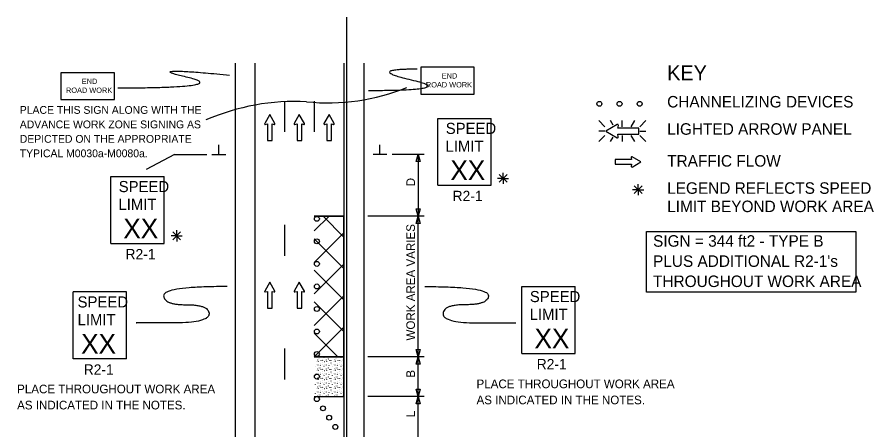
# Model space of a CAD drawing. Extents: x 16247 to 18479, y 5687 to 6964.
# Drawn here: x 16736 to 17429, y 6630 to 6964 of the extents above; entities that cross this region are included whole.
import ezdxf

# ---------------------------------------------------------------- set-up
doc = ezdxf.new("R2010")
doc.units = 0
for name, color, linetype in [('ALI_LEGAL_EX', 7, 'Continuous'), ('MT_SCRATCH_LEVEL_E', 7, 'Continuous'), ('PAVT_EDGE_EX', 7, 'Continuous'), ('TRAFFIC_SIGNS_PR', 7, 'Continuous'), ('TYPICAL_TEXT_DIMEN_EX', 7, 'Continuous'), ('TYPICAL_TEXT_DIMEN_PR', 7, 'Continuous')]:
    doc.layers.add(name, color=color, linetype=linetype)

msp = doc.modelspace()

# ---------------------------------------------------------------- linework, layer by layer
at = {"layer": 'ALI_LEGAL_EX'}
msp.add_line((17002.72, 6964.07), (17002.72, 6147.1), dxfattribs=at)
for points in [[(16952.72, 6896.22), (16952.72, 6871.22)], [(16976.72, 6896.22), (16976.72, 6871.22)], [(16952.72, 6796.22), (16952.72, 6771.22)], [(16952.72, 6696.22), (16952.72, 6671.22)]]:
    msp.add_lwpolyline(points, dxfattribs=at)
at = {"layer": 'MT_SCRATCH_LEVEL_E'}
for p, q in [((16940.72, 6885.31), (16936.61, 6878.07)), ((16944.87, 6878.07), (16940.72, 6885.31)), ((16964.62, 6885.31), (16960.51, 6878.07)), ((16968.77, 6878.07), (16964.62, 6885.31)), ((16988.68, 6885.31), (16984.56, 6878.07)), ((16992.82, 6878.07), (16988.68, 6885.31)), ((16937.09, 6877.38), (16938.87, 6877.7)), ((16938.87, 6877.7), (16938.87, 6864.44)), ((16942.61, 6864.44), (16942.61, 6877.7)), ((16942.61, 6877.7), (16944.39, 6877.38)), ((16960.99, 6877.38), (16962.77, 6877.7)), ((16962.77, 6877.7), (16962.77, 6864.44)), ((16966.51, 6864.44), (16966.51, 6877.7)), ((16966.51, 6877.7), (16968.29, 6877.38)), ((16985.05, 6877.38), (16986.82, 6877.7)), ((16986.82, 6877.7), (16986.82, 6864.44)), ((16990.57, 6864.44), (16990.57, 6877.7)), ((16990.57, 6877.7), (16992.34, 6877.38)), ((16938.87, 6864.44), (16942.61, 6864.44)), ((16962.77, 6864.44), (16966.51, 6864.44)), ((16986.82, 6864.44), (16990.57, 6864.44)), ((17233.37, 6848.9), (17220.11, 6848.9)), ((17220.11, 6848.9), (17220.11, 6845.16)), ((17233.05, 6850.68), (17233.37, 6848.9)), ((17240.98, 6847.05), (17233.74, 6851.16)), ((17220.11, 6845.16), (17233.37, 6845.16)), ((17233.37, 6845.16), (17233.05, 6843.39)), ((17233.74, 6842.91), (17240.98, 6847.05)), ((16940.72, 6749.79), (16936.61, 6742.55)), ((16944.87, 6742.55), (16940.72, 6749.79)), ((16964.62, 6749.79), (16960.51, 6742.55)), ((16968.77, 6742.55), (16964.62, 6749.79)), ((16937.09, 6741.86), (16938.87, 6742.18)), ((16938.87, 6742.18), (16938.87, 6728.92)), ((16942.61, 6728.92), (16942.61, 6742.18)), ((16942.61, 6742.18), (16944.39, 6741.86)), ((16960.99, 6741.86), (16962.77, 6742.18)), ((16962.77, 6742.18), (16962.77, 6728.92)), ((16966.51, 6728.92), (16966.51, 6742.18)), ((16966.51, 6742.18), (16968.29, 6741.86)), ((16938.87, 6728.92), (16942.61, 6728.92)), ((16962.77, 6728.92), (16966.51, 6728.92))]:
    msp.add_line(p, q, dxfattribs=at)
for centre, start, end in [((16937.02, 6877.84), 150.42484, 279.96381), ((16944.46, 6877.84), 260.03619, 29.77312), ((16960.92, 6877.84), 150.42484, 279.96381), ((16968.36, 6877.84), 260.03619, 29.77312), ((16984.97, 6877.84), 150.42484, 279.96381), ((16992.41, 6877.84), 260.03619, 29.77312), ((17233.51, 6850.76), 60.42484, 189.96381), ((17233.51, 6843.32), 170.03619, 299.77312), ((16937.02, 6742.32), 150.42484, 279.96381), ((16944.46, 6742.32), 260.03619, 29.77312), ((16960.92, 6742.32), 150.42484, 279.96381), ((16968.36, 6742.32), 260.03619, 29.77312)]:
    msp.add_arc(centre, 0.463, start, end, dxfattribs=at)
at = {"layer": 'PAVT_EDGE_EX'}
for p, q in [((16912.72, 6926.76), (16912.72, 6233.21)), ((16928.72, 6926.76), (16928.72, 6233.21)), ((17000.72, 6926.76), (17000.72, 6233.21)), ((17016.72, 6926.76), (17016.72, 6233.21)), ((17000.72, 6803.12), (16976.72, 6803.12)), ((16976.72, 6803.12), (17000.72, 6803.12)), ((16976.72, 6791.22), (16988.62, 6803.12)), ((17000.72, 6786.31), (16983.91, 6803.12)), ((17000.72, 6689.4), (17000.72, 6803.12)), ((16976.72, 6765.77), (17000.72, 6789.77)), ((17000.72, 6760.86), (16976.72, 6784.86)), ((16976.72, 6740.31), (17000.72, 6764.31)), ((17000.72, 6735.4), (16976.72, 6759.4)), ((16976.72, 6714.86), (17000.72, 6738.86)), ((17000.72, 6709.95), (16976.72, 6733.95)), ((16976.72, 6689.4), (17000.72, 6713.4)), ((16995.81, 6689.4), (16976.72, 6708.49)), ((16976.72, 6689.4), (17000.72, 6689.4)), ((16976.72, 6689.4), (17000.72, 6689.4)), ((17000.72, 6689.4), (16976.72, 6689.4)), ((16976.72, 6689.4), (16976.72, 6689.4)), ((16977.65, 6689.04), (16977.7, 6689.16)), ((16984.53, 6689.04), (16984.59, 6689.16)), ((16991.42, 6689.04), (16991.47, 6689.16)), ((16998.31, 6689.04), (16998.36, 6689.16)), ((17000.72, 6657.34), (17000.72, 6689.4)), ((16977.65, 6681.76), (16977.7, 6681.87)), ((16978.22, 6685.72), (16978.27, 6685.64)), ((16978.27, 6683.51), (16978.32, 6683.43)), ((16979.55, 6682.93), (16979.56, 6682.82)), ((16979.67, 6686.84), (16979.72, 6686.96)), ((16979.75, 6685.58), (16979.8, 6685.5)), ((16980.43, 6687.8), (16980.48, 6687.73)), ((16981.17, 6687.78), (16981.22, 6687.7)), ((16981.39, 6683.79), (16981.44, 6683.9)), ((16981.58, 6682.59), (16981.63, 6682.51)), ((16982.04, 6686.4), (16982.09, 6686.32)), ((16983.31, 6684.66), (16983.37, 6684.58)), ((16983.36, 6683.26), (16983.41, 6683.37)), ((16983.49, 6686.55), (16983.54, 6686.66)), ((16984.53, 6681.76), (16984.59, 6681.87)), ((16985.1, 6685.72), (16985.16, 6685.64)), ((16985.15, 6683.51), (16985.21, 6683.43)), ((16986.44, 6682.93), (16986.45, 6682.82)), ((16986.56, 6686.84), (16986.61, 6686.96)), ((16986.64, 6685.58), (16986.69, 6685.5)), ((16987.32, 6687.8), (16987.37, 6687.73)), ((16988.06, 6687.78), (16988.11, 6687.7)), ((16988.28, 6683.79), (16988.33, 6683.9)), ((16988.47, 6682.59), (16988.52, 6682.51)), ((16988.92, 6686.4), (16988.98, 6686.32)), ((16990.2, 6684.66), (16990.25, 6684.58)), ((16990.24, 6683.26), (16990.3, 6683.37)), ((16990.37, 6686.55), (16990.42, 6686.66)), ((16991.42, 6681.76), (16991.47, 6681.87)), ((16991.99, 6685.72), (16992.04, 6685.64)), ((16992.04, 6683.51), (16992.09, 6683.43)), ((16993.32, 6682.93), (16993.33, 6682.82)), ((16993.44, 6686.84), (16993.49, 6686.96)), ((16993.52, 6685.58), (16993.57, 6685.5)), ((16994.21, 6687.8), (16994.26, 6687.73)), ((16994.94, 6687.78), (16994.99, 6687.7)), ((16995.16, 6683.79), (16995.22, 6683.9)), ((16995.35, 6682.59), (16995.4, 6682.51)), ((16995.81, 6686.4), (16995.86, 6686.32)), ((16997.09, 6684.66), (16997.14, 6684.58)), ((16997.13, 6683.26), (16997.18, 6683.37)), ((16997.26, 6686.55), (16997.31, 6686.66)), ((16998.31, 6681.76), (16998.36, 6681.87)), ((16998.88, 6685.72), (16998.93, 6685.64)), ((16998.93, 6683.51), (16998.98, 6683.43)), ((17000.21, 6682.93), (17000.22, 6682.82)), ((17000.33, 6686.84), (17000.38, 6686.96)), ((17000.41, 6685.58), (17000.46, 6685.5)), ((16977.65, 6674.47), (16977.7, 6674.59)), ((16978.22, 6678.43), (16978.27, 6678.36)), ((16978.27, 6676.22), (16978.32, 6676.15)), ((16979.55, 6675.65), (16979.56, 6675.53)), ((16979.67, 6679.56), (16979.72, 6679.68)), ((16979.75, 6678.29), (16979.8, 6678.22)), ((16980.43, 6680.52), (16980.48, 6680.44)), ((16981.17, 6680.49), (16981.22, 6680.41)), ((16981.39, 6676.5), (16981.44, 6676.62)), ((16981.58, 6675.31), (16981.63, 6675.23)), ((16982.04, 6679.11), (16982.09, 6679.03)), ((16983.31, 6677.37), (16983.37, 6677.3)), ((16983.36, 6675.97), (16983.41, 6676.09)), ((16983.49, 6679.26), (16983.54, 6679.38)), ((16984.53, 6674.47), (16984.59, 6674.59)), ((16985.1, 6678.43), (16985.16, 6678.36)), ((16985.15, 6676.22), (16985.21, 6676.15)), ((16986.44, 6675.65), (16986.45, 6675.53)), ((16986.56, 6679.56), (16986.61, 6679.68)), ((16986.64, 6678.29), (16986.69, 6678.22)), ((16987.32, 6680.52), (16987.37, 6680.44)), ((16988.06, 6680.49), (16988.11, 6680.41)), ((16988.28, 6676.5), (16988.33, 6676.62)), ((16988.47, 6675.31), (16988.52, 6675.23)), ((16988.92, 6679.11), (16988.98, 6679.03)), ((16990.2, 6677.37), (16990.25, 6677.3)), ((16990.24, 6675.97), (16990.3, 6676.09)), ((16990.37, 6679.26), (16990.42, 6679.38)), ((16991.42, 6674.47), (16991.47, 6674.59)), ((16991.99, 6678.43), (16992.04, 6678.36)), ((16992.04, 6676.22), (16992.09, 6676.15)), ((16993.32, 6675.65), (16993.33, 6675.53)), ((16993.44, 6679.56), (16993.49, 6679.68)), ((16993.52, 6678.29), (16993.57, 6678.22)), ((16994.21, 6680.52), (16994.26, 6680.44)), ((16994.94, 6680.49), (16994.99, 6680.41)), ((16995.16, 6676.5), (16995.22, 6676.62)), ((16995.35, 6675.31), (16995.4, 6675.23)), ((16995.81, 6679.11), (16995.86, 6679.03)), ((16997.09, 6677.37), (16997.14, 6677.3)), ((16997.13, 6675.97), (16997.18, 6676.09)), ((16997.26, 6679.26), (16997.31, 6679.38)), ((16998.31, 6674.47), (16998.36, 6674.59)), ((16998.88, 6678.43), (16998.93, 6678.36)), ((16998.93, 6676.22), (16998.98, 6676.15)), ((17000.21, 6675.65), (17000.22, 6675.53)), ((17000.33, 6679.56), (17000.38, 6679.68)), ((17000.41, 6678.29), (17000.46, 6678.22)), ((16977.65, 6667.19), (16977.7, 6667.3)), ((16978.22, 6671.15), (16978.27, 6671.07)), ((16978.27, 6668.94), (16978.32, 6668.86)), ((16979.55, 6668.36), (16979.56, 6668.25)), ((16979.67, 6672.28), (16979.72, 6672.39)), ((16979.75, 6671.01), (16979.8, 6670.93)), ((16980.43, 6673.23), (16980.48, 6673.16)), ((16981.17, 6673.2), (16981.22, 6673.13)), ((16981.39, 6669.22), (16981.44, 6669.34)), ((16981.58, 6668.02), (16981.63, 6667.94)), ((16982.04, 6671.83), (16982.09, 6671.75)), ((16983.31, 6670.09), (16983.37, 6670.01)), ((16983.36, 6668.69), (16983.41, 6668.81)), ((16983.49, 6671.98), (16983.54, 6672.09)), ((16984.53, 6667.19), (16984.59, 6667.3)), ((16985.1, 6671.15), (16985.16, 6671.07)), ((16985.15, 6668.94), (16985.21, 6668.86)), ((16986.44, 6668.36), (16986.45, 6668.25)), ((16986.56, 6672.28), (16986.61, 6672.39)), ((16986.64, 6671.01), (16986.69, 6670.93)), ((16987.32, 6673.23), (16987.37, 6673.16)), ((16988.06, 6673.2), (16988.11, 6673.13)), ((16988.28, 6669.22), (16988.33, 6669.34)), ((16988.47, 6668.02), (16988.52, 6667.94)), ((16988.92, 6671.83), (16988.98, 6671.75)), ((16990.2, 6670.09), (16990.25, 6670.01)), ((16990.24, 6668.69), (16990.3, 6668.81)), ((16990.37, 6671.98), (16990.42, 6672.09)), ((16991.42, 6667.19), (16991.47, 6667.3)), ((16991.99, 6671.15), (16992.04, 6671.07)), ((16992.04, 6668.94), (16992.09, 6668.86)), ((16993.32, 6668.36), (16993.33, 6668.25)), ((16993.44, 6672.28), (16993.49, 6672.39)), ((16993.52, 6671.01), (16993.57, 6670.93)), ((16994.21, 6673.23), (16994.26, 6673.16)), ((16994.94, 6673.2), (16994.99, 6673.13)), ((16995.16, 6669.22), (16995.22, 6669.34)), ((16995.35, 6668.02), (16995.4, 6667.94)), ((16995.81, 6671.83), (16995.86, 6671.75)), ((16997.09, 6670.09), (16997.14, 6670.01)), ((16997.13, 6668.69), (16997.18, 6668.81)), ((16997.26, 6671.98), (16997.31, 6672.09)), ((16998.31, 6667.19), (16998.36, 6667.3)), ((16998.88, 6671.15), (16998.93, 6671.07)), ((16998.93, 6668.94), (16998.98, 6668.86)), ((17000.21, 6668.36), (17000.22, 6668.25)), ((17000.33, 6672.28), (17000.38, 6672.39)), ((17000.41, 6671.01), (17000.46, 6670.93)), ((16978.22, 6663.86), (16978.27, 6663.79)), ((16978.27, 6661.65), (16978.32, 6661.58)), ((16979.55, 6661.08), (16979.56, 6660.96)), ((16979.67, 6664.99), (16979.72, 6665.11)), ((16979.75, 6663.72), (16979.8, 6663.65)), ((16980.43, 6665.95), (16980.48, 6665.87)), ((16981.17, 6665.92), (16981.22, 6665.84)), ((16981.39, 6661.93), (16981.44, 6662.05)), ((16981.58, 6660.74), (16981.63, 6660.66)), ((16982.04, 6664.54), (16982.09, 6664.46)), ((16983.31, 6662.8), (16983.37, 6662.73)), ((16983.36, 6661.4), (16983.41, 6661.52)), ((16983.49, 6664.69), (16983.54, 6664.81)), ((16985.1, 6663.86), (16985.16, 6663.79)), ((16985.15, 6661.65), (16985.21, 6661.58)), ((16986.44, 6661.08), (16986.45, 6660.96)), ((16986.56, 6664.99), (16986.61, 6665.11)), ((16986.64, 6663.72), (16986.69, 6663.65)), ((16987.32, 6665.95), (16987.37, 6665.87)), ((16988.06, 6665.92), (16988.11, 6665.84)), ((16988.28, 6661.93), (16988.33, 6662.05)), ((16988.47, 6660.74), (16988.52, 6660.66)), ((16988.92, 6664.54), (16988.98, 6664.46)), ((16990.2, 6662.8), (16990.25, 6662.73)), ((16990.24, 6661.4), (16990.3, 6661.52)), ((16990.37, 6664.69), (16990.42, 6664.81)), ((16991.99, 6663.86), (16992.04, 6663.79)), ((16992.04, 6661.65), (16992.09, 6661.58)), ((16993.32, 6661.08), (16993.33, 6660.96)), ((16993.44, 6664.99), (16993.49, 6665.11)), ((16993.52, 6663.72), (16993.57, 6663.65)), ((16994.21, 6665.95), (16994.26, 6665.87)), ((16994.94, 6665.92), (16994.99, 6665.84)), ((16995.16, 6661.93), (16995.22, 6662.05)), ((16995.35, 6660.74), (16995.4, 6660.66)), ((16995.81, 6664.54), (16995.86, 6664.46)), ((16997.09, 6662.8), (16997.14, 6662.73)), ((16997.13, 6661.4), (16997.18, 6661.52)), ((16997.26, 6664.69), (16997.31, 6664.81)), ((16998.88, 6663.86), (16998.93, 6663.79)), ((16998.93, 6661.65), (16998.98, 6661.58)), ((17000.21, 6661.08), (17000.22, 6660.96)), ((17000.33, 6664.99), (17000.38, 6665.11)), ((17000.41, 6663.72), (17000.46, 6663.65)), ((16976.72, 6657.34), (17000.72, 6657.34)), ((16976.72, 6657.34), (17000.72, 6657.34)), ((16977.65, 6659.9), (16977.7, 6660.02)), ((16979.67, 6657.7), (16979.72, 6657.82)), ((16980.43, 6658.66), (16980.48, 6658.59)), ((16981.17, 6658.64), (16981.22, 6658.56)), ((16983.49, 6657.41), (16983.54, 6657.52)), ((16984.53, 6659.9), (16984.59, 6660.02)), ((16986.56, 6657.7), (16986.61, 6657.82)), ((16987.32, 6658.66), (16987.37, 6658.59)), ((16988.06, 6658.64), (16988.11, 6658.56)), ((16990.37, 6657.41), (16990.42, 6657.52)), ((16991.42, 6659.9), (16991.47, 6660.02)), ((16993.44, 6657.7), (16993.49, 6657.82)), ((16994.21, 6658.66), (16994.26, 6658.59)), ((16994.94, 6658.64), (16994.99, 6658.56)), ((16997.26, 6657.41), (16997.31, 6657.52)), ((16998.31, 6659.9), (16998.36, 6660.02)), ((17000.33, 6657.7), (17000.38, 6657.82))]:
    msp.add_line(p, q, dxfattribs=at)
at = {"layer": 'TRAFFIC_SIGNS_PR'}
for p, q in [((17076.58, 6882.17), (17119.78, 6882.17)), ((17076.58, 6828.17), (17076.58, 6882.17)), ((17119.78, 6828.17), (17119.78, 6882.17)), ((17206.79, 6880.44), (17211.72, 6875.5)), ((17218.55, 6876.61), (17216.34, 6880.44)), ((17225.87, 6875.5), (17225.87, 6880.44)), ((17233.11, 6875.5), (17235.96, 6880.44)), ((17240.02, 6875.5), (17244.96, 6880.44)), ((17211.72, 6871.95), (17206.79, 6871.95)), ((17206.79, 6863.46), (17211.72, 6868.39)), ((17225.87, 6868.39), (17225.87, 6863.46)), ((17236, 6863.46), (17233.15, 6868.39)), ((17240.02, 6871.95), (17244.96, 6871.95)), ((17240.02, 6868.39), (17244.96, 6863.45)), ((17216.3, 6863.46), (17218.41, 6867.12)), ((16812.01, 6835.14), (16855.21, 6835.14)), ((16812.01, 6781.14), (16812.01, 6835.14)), ((16855.21, 6781.14), (16855.21, 6835.14)), ((17076.58, 6828.17), (17119.78, 6828.17)), ((16812.01, 6781.14), (16855.21, 6781.14)), ((17144.63, 6746.22), (17187.83, 6746.22)), ((17144.63, 6692.22), (17144.63, 6746.22)), ((17187.83, 6692.22), (17187.83, 6746.22)), ((16824.83, 6741.87), (16781.63, 6741.87)), ((16781.63, 6687.87), (16781.63, 6741.87)), ((16824.83, 6687.87), (16824.83, 6741.87)), ((17144.63, 6692.22), (17187.83, 6692.22)), ((16824.83, 6687.87), (16781.63, 6687.87))]:
    msp.add_line(p, q, dxfattribs=at)
for points in [[(16771.8, 6897.5), (16815, 6897.5), (16815, 6919.1), (16771.8, 6919.1)], [(17062.94, 6901.91), (17106.14, 6901.91), (17106.14, 6923.51), (17062.94, 6923.51)], [(17062.94, 6901.91), (17106.14, 6901.91), (17106.14, 6923.51), (17062.94, 6923.51)]]:
    msp.add_lwpolyline(points, close=True, dxfattribs=at)
for points in [[(17221.8, 6877.22), (17212.51, 6871.95), (17221.8, 6866.63)], [(17222.67, 6867.25), (17222.27, 6869.52), (17239.29, 6869.52), (17239.29, 6874.32), (17222.27, 6874.32), (17222.68, 6876.6)]]:
    msp.add_lwpolyline(points, dxfattribs=at)
for centre in [(17207.35, 6893.98), (17223.65, 6893.98), (17239.95, 6893.98), (16978.82, 6801), (16978.82, 6782.79), (16978.82, 6764.57), (16978.82, 6746.36), (16978.82, 6728.15), (16978.82, 6709.93), (16978.82, 6691.72), (16978.82, 6673.5), (16978.82, 6655.29), (16983.79, 6647.78), (16988.76, 6640.27), (16993.73, 6632.77)]:
    msp.add_circle(centre, 2, dxfattribs=at)
for centre, radius, start, end in [((16988.38, 7060.49), 165.74, 263.81853, 292.44581), ((16961.52, 6713.48), 182.45, 87.16713, 113.38058), ((17222.09, 6876.7), 0.598, 350.73078, 118.89165), ((17222.09, 6867.15), 0.597, 241.48329, 9.95933)]:
    msp.add_arc(centre, radius, start, end, dxfattribs=at)
for points in [[(16817.69, 6906.91), (16911.43, 6906.91), (16834.91, 6924.32), (16908.24, 6917.25)], [(17059.88, 6921.99), (17017.37, 6921.99), (17093.89, 6904.57), (17020.55, 6904.57)]]:
    msp.add_open_spline(points, degree=2, dxfattribs=at)
at = {"layer": 'TYPICAL_TEXT_DIMEN_EX'}
msp.add_lwpolyline([(17245.38, 6790.88), (17414.83, 6790.88), (17414.83, 6741.68), (17245.38, 6741.68)], close=True, dxfattribs=at)
at = {"layer": 'TYPICAL_TEXT_DIMEN_PR'}
for p, q in [((16899.6, 6853.12), (16899.6, 6860.91)), ((17029.85, 6853.12), (17029.85, 6860.91)), ((16863.72, 6853.12), (16840.61, 6840.94)), ((16863.72, 6853.12), (16889.72, 6853.12)), ((16893.97, 6853.12), (16905.22, 6853.12)), ((17035.47, 6853.12), (17024.22, 6853.12)), ((17065.72, 6853.12), (17039.72, 6853.12)), ((17059.15, 6847.26), (17060.72, 6853.12)), ((17060.72, 6853.12), (17062.29, 6847.26)), ((17060.72, 6853.12), (17060.72, 6803.12)), ((17060.72, 6847.26), (17059.15, 6847.26)), ((17062.29, 6847.26), (17060.72, 6847.26)), ((17129.48, 6833.74), (17124.95, 6833.74)), ((17126.3, 6836.93), (17132.67, 6830.55)), ((17132.67, 6836.93), (17126.3, 6830.55)), ((17129.48, 6833.74), (17129.48, 6838.2)), ((17129.48, 6833.74), (17132.67, 6833.74)), ((17129.48, 6833.74), (17133.96, 6833.74)), ((17129.48, 6833.74), (17129.48, 6829.24)), ((17235.58, 6827.78), (17241.95, 6821.4)), ((17241.95, 6827.78), (17235.58, 6821.4)), ((17238.76, 6824.59), (17238.76, 6829.05)), ((17238.76, 6824.59), (17234.23, 6824.59)), ((17238.76, 6824.59), (17241.95, 6824.59)), ((17238.76, 6824.59), (17243.24, 6824.59)), ((17238.76, 6824.59), (17238.76, 6820.09)), ((17060.72, 6803.12), (17059.15, 6808.99)), ((17059.15, 6808.99), (17060.72, 6808.99)), ((17060.72, 6808.99), (17062.29, 6808.99)), ((17062.29, 6808.99), (17060.72, 6803.12)), ((17065.72, 6803.12), (17020.02, 6803.12)), ((17059.15, 6797.26), (17060.72, 6803.12)), ((17060.72, 6689.4), (17060.72, 6803.12)), ((17060.72, 6803.12), (17062.29, 6797.26)), ((17060.72, 6797.26), (17059.15, 6797.26)), ((17062.29, 6797.26), (17060.72, 6797.26)), ((16865.4, 6787.3), (16860.87, 6787.3)), ((16862.22, 6790.49), (16868.59, 6784.11)), ((16868.59, 6790.49), (16862.22, 6784.11)), ((16865.4, 6787.3), (16865.4, 6791.76)), ((16865.4, 6787.3), (16868.59, 6787.3)), ((16865.4, 6787.3), (16869.88, 6787.3)), ((16865.4, 6787.3), (16865.4, 6782.8)), ((17060.72, 6689.4), (17059.15, 6695.26)), ((17059.15, 6695.26), (17060.72, 6695.26)), ((17060.72, 6695.26), (17062.29, 6695.26)), ((17062.29, 6695.26), (17060.72, 6689.4)), ((17065.72, 6689.4), (17020.02, 6689.4)), ((17059.15, 6683.54), (17060.72, 6689.4)), ((17060.72, 6657.34), (17060.72, 6689.4)), ((17060.72, 6689.4), (17062.29, 6683.54)), ((17060.72, 6683.54), (17059.15, 6683.54)), ((17062.29, 6683.54), (17060.72, 6683.54)), ((17060.72, 6657.34), (17059.15, 6663.2)), ((17059.15, 6663.2), (17060.72, 6663.2)), ((17060.72, 6663.2), (17062.29, 6663.2)), ((17062.29, 6663.2), (17060.72, 6657.34)), ((17065.72, 6657.34), (17020.02, 6657.34)), ((17059.15, 6651.48), (17060.72, 6657.34)), ((17060.72, 6623.15), (17060.72, 6657.34)), ((17060.72, 6657.34), (17062.29, 6651.48)), ((17060.72, 6651.48), (17059.15, 6651.48)), ((17062.29, 6651.48), (17060.72, 6651.48))]:
    msp.add_line(p, q, dxfattribs=at)
for points in [[(16906.3, 6746.26), (16854.85, 6746.26), (16854.85, 6731.56), (16891.6, 6731.56), (16891.6, 6716.86), (16832.8, 6716.86), (16832.8, 6716.86)], [(17066.17, 6746.26), (17117.62, 6746.26), (17117.62, 6731.56), (17080.87, 6731.56), (17080.87, 6716.86), (17139.67, 6716.86), (17139.67, 6716.86)]]:
    msp.add_open_spline(points, degree=2, dxfattribs=at)

# ---------------------------------------------------------------- texts
at = {"layer": 'TRAFFIC_SIGNS_PR'}
for s, height, p in [('END', 4.31, (17079.82, 6914.43)), ('END', 4.31, (17079.82, 6914.43)), ('END', 4.31, (16788.67, 6910.02)), ('ROAD WORK', 4.31, (17067, 6907.24)), ('ROAD WORK', 4.31, (17067, 6907.24)), ('ROAD WORK', 4.31, (16775.86, 6902.83)), ('PLACE THIS SIGN ALONG WITH THE', 6.3, (16738.49, 6885.91)), ('ADVANCE WORK ZONE SIGNING AS', 6.3, (16738.49, 6874.21)), ('SPEED', 9, (17083.07, 6869.64)), ('DEPICTED ON THE APPROPRIATE', 6.3, (16738.49, 6862.51)), ('LIMIT', 9, (17082.89, 6855.24)), ('TYPICAL M0030a-M0080a.', 6.3, (16738.49, 6850.81)), ('XX', 15.785, (17086.83, 6832.4)), ('SPEED', 9, (16818.5, 6822.61)), ('R2-1', 8.37, (17088.59, 6815.3)), ('LIMIT', 9, (16818.31, 6808.21)), ('XX', 15.785, (16822.26, 6785.37)), ('R2-1', 8.37, (16824.02, 6768.27)), ('SPEED', 9, (16785.25, 6729.34)), ('SPEED', 9, (17151.11, 6733.68)), ('LIMIT', 9, (16785.22, 6714.94)), ('LIMIT', 9, (17150.93, 6719.28)), ('XX', 15.785, (17154.88, 6696.44)), ('XX', 15.785, (16788.14, 6692.1)), ('R2-1', 8.37, (16790.22, 6675)), ('R2-1', 8.37, (17156.64, 6679.35)), ('PLACE THROUGHOUT WORK AREA', 7, (17107.98, 6664.09)), ('PLACE THROUGHOUT WORK AREA', 7, (16736.32, 6659.93)), ('AS INDICATED IN THE NOTES.', 7, (16736.32, 6646.93)), ('AS INDICATED IN THE NOTES.', 7, (17107.98, 6651.09))]:
    msp.add_text(s, height=height, dxfattribs=at).set_placement(p)
at = {"layer": 'TYPICAL_TEXT_DIMEN_EX'}
for s, height, p in [('KEY', 12, (17262.19, 6913.09)), ('CHANNELIZING DEVICES', 9.3, (17262.19, 6891.04)), ('LIGHTED ARROW PANEL', 9.3, (17262.19, 6868.99)), ('TRAFFIC FLOW', 9.3, (17262.19, 6843.19)), ('LEGEND REFLECTS SPEED', 9.3, (17262.19, 6821.24)), ('LIMIT BEYOND WORK AREA', 9.3, (17262.19, 6806.44)), ('SIGN = 344 ft2 - TYPE B', 9.3, (17250.77, 6778.47)), ("PLUS ADDITIONAL R2-1's", 9.3, (17250.77, 6762.17)), ('THROUGHOUT WORK AREA', 9.3, (17250.77, 6745.87))]:
    msp.add_text(s, height=height, dxfattribs=at).set_placement(p)
at = {"layer": 'TYPICAL_TEXT_DIMEN_PR'}
for s, p in [('D', (17058.16, 6827.34)), ('WORK AREA VARIES', (17058.16, 6702.62)), ('B', (17058.16, 6672.6)), ('L', (17058.16, 6640.63))]:
    msp.add_text(s, height=7, rotation=90, dxfattribs=at).set_placement(p)

doc.saveas('drawing.dxf')
